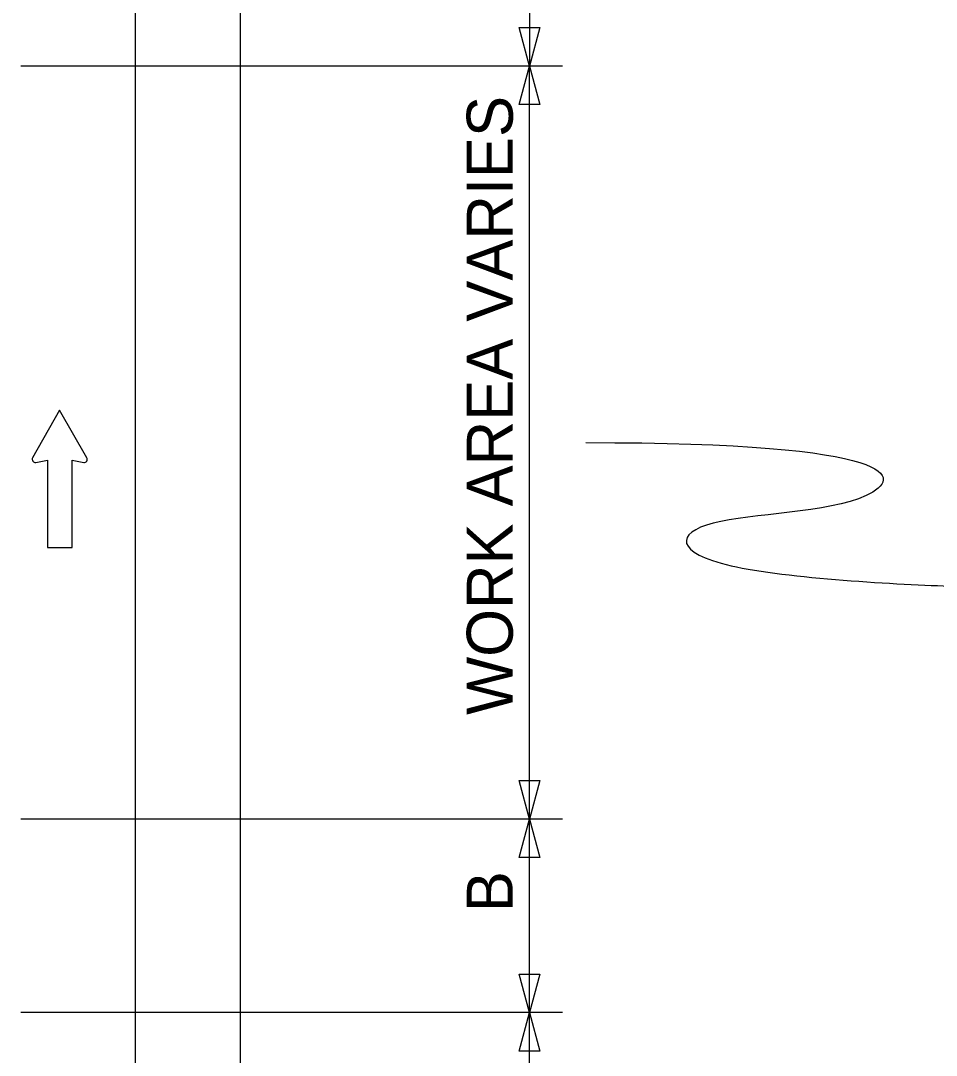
# Model space of a CAD drawing. Extents: x 16734 to 18475, y 5704 to 7011.
# Drawn here: x 16990.5 to 17129.7, y 6636.8 to 6794.2 of the extents above; entities that cross this region are included whole.
import ezdxf

# ---------------------------------------------------------------- set-up
doc = ezdxf.new("R2010")
doc.units = 0
for name, color, linetype in [('MT_SCRATCH_LEVEL_E', 7, 'Continuous'), ('PAVT_EDGE_EX', 7, 'Continuous'), ('TYPICAL_TEXT_DIMEN_PR', 7, 'Continuous')]:
    doc.layers.add(name, color=color, linetype=linetype)

msp = doc.modelspace()

# ---------------------------------------------------------------- linework, layer by layer
at = {"layer": 'MT_SCRATCH_LEVEL_E'}
for p, q in [((16996.38, 6734.95), (16992.27, 6727.71)), ((16996.38, 6734.95), (16992.27, 6727.71)), ((17000.53, 6727.71), (16996.38, 6734.95)), ((17000.53, 6727.71), (16996.38, 6734.95)), ((16992.75, 6727.02), (16994.53, 6727.34)), ((16992.75, 6727.02), (16994.53, 6727.34)), ((16994.53, 6727.34), (16994.53, 6714.08)), ((16994.53, 6727.34), (16994.53, 6714.08)), ((16998.27, 6714.08), (16998.27, 6727.34)), ((16998.27, 6727.34), (17000.05, 6727.02)), ((16998.27, 6714.08), (16998.27, 6727.34)), ((16998.27, 6727.34), (17000.05, 6727.02)), ((16994.53, 6714.08), (16998.27, 6714.08)), ((16994.53, 6714.08), (16998.27, 6714.08))]:
    msp.add_line(p, q, dxfattribs=at)
for centre, start, end in [((16992.68, 6727.48), 150.4248, 279.9638), ((16992.68, 6727.48), 150.4248, 279.9638), ((17000.12, 6727.48), 260.0362, 29.7731), ((17000.12, 6727.48), 260.0362, 29.7731)]:
    msp.add_arc(centre, 0.463, start, end, dxfattribs=at)
at = {"layer": 'PAVT_EDGE_EX'}
for p, q in [((17007.85, 6920.73), (17007.85, 6024.13)), ((17023.85, 6920.73), (17023.85, 6024.13))]:
    msp.add_line(p, q, dxfattribs=at)
at = {"layer": 'TYPICAL_TEXT_DIMEN_PR'}
for p, q in [((17067.85, 6837.3), (17067.85, 6787.3)), ((17067.85, 6787.3), (17066.28, 6793.16)), ((17066.28, 6793.16), (17067.85, 6793.16)), ((17067.85, 6793.16), (17069.42, 6793.16)), ((17069.42, 6793.16), (17067.85, 6787.3)), ((17072.85, 6787.3), (16990.46, 6787.3)), ((17066.28, 6781.43), (17067.85, 6787.3)), ((17067.85, 6672.76), (17067.85, 6787.3)), ((17067.85, 6787.3), (17069.42, 6781.43)), ((17067.85, 6781.43), (17066.28, 6781.43)), ((17069.42, 6781.43), (17067.85, 6781.43)), ((17067.85, 6672.76), (17066.28, 6678.62)), ((17066.28, 6678.62), (17067.85, 6678.62)), ((17067.85, 6678.62), (17069.42, 6678.62)), ((17069.42, 6678.62), (17067.85, 6672.76)), ((17072.85, 6672.76), (16990.46, 6672.76)), ((17066.28, 6666.9), (17067.85, 6672.76)), ((17067.85, 6643.33), (17067.85, 6672.76)), ((17067.85, 6672.76), (17069.42, 6666.9)), ((17067.85, 6666.9), (17066.28, 6666.9)), ((17069.42, 6666.9), (17067.85, 6666.9)), ((17067.85, 6643.33), (17066.28, 6649.19)), ((17066.28, 6649.19), (17067.85, 6649.19)), ((17067.85, 6649.19), (17069.42, 6649.19)), ((17069.42, 6649.19), (17067.85, 6643.33)), ((17072.85, 6643.33), (16990.46, 6643.33)), ((17066.28, 6637.47), (17067.85, 6643.33)), ((17067.85, 6612.77), (17067.85, 6643.33)), ((17067.85, 6643.33), (17069.42, 6637.47)), ((17067.85, 6637.47), (17066.28, 6637.47)), ((17069.42, 6637.47), (17067.85, 6637.47))]:
    msp.add_line(p, q, dxfattribs=at)
msp.add_open_spline([(17076.4, 6730.03), (17124.86, 6730.03), (17124.86, 6719.28), (17089.95, 6719.28), (17089.95, 6710.23), (17124.15, 6708.46), (17132.44, 6708.17)], degree=3, dxfattribs=at)

# ---------------------------------------------------------------- texts
for s, p in [('WORK AREA VARIES', (17065.3, 6688.61)), ('B', (17065.3, 6658.6))]:
    msp.add_text(s, height=7, rotation=90, dxfattribs=at).set_placement(p)

doc.saveas('drawing.dxf')
